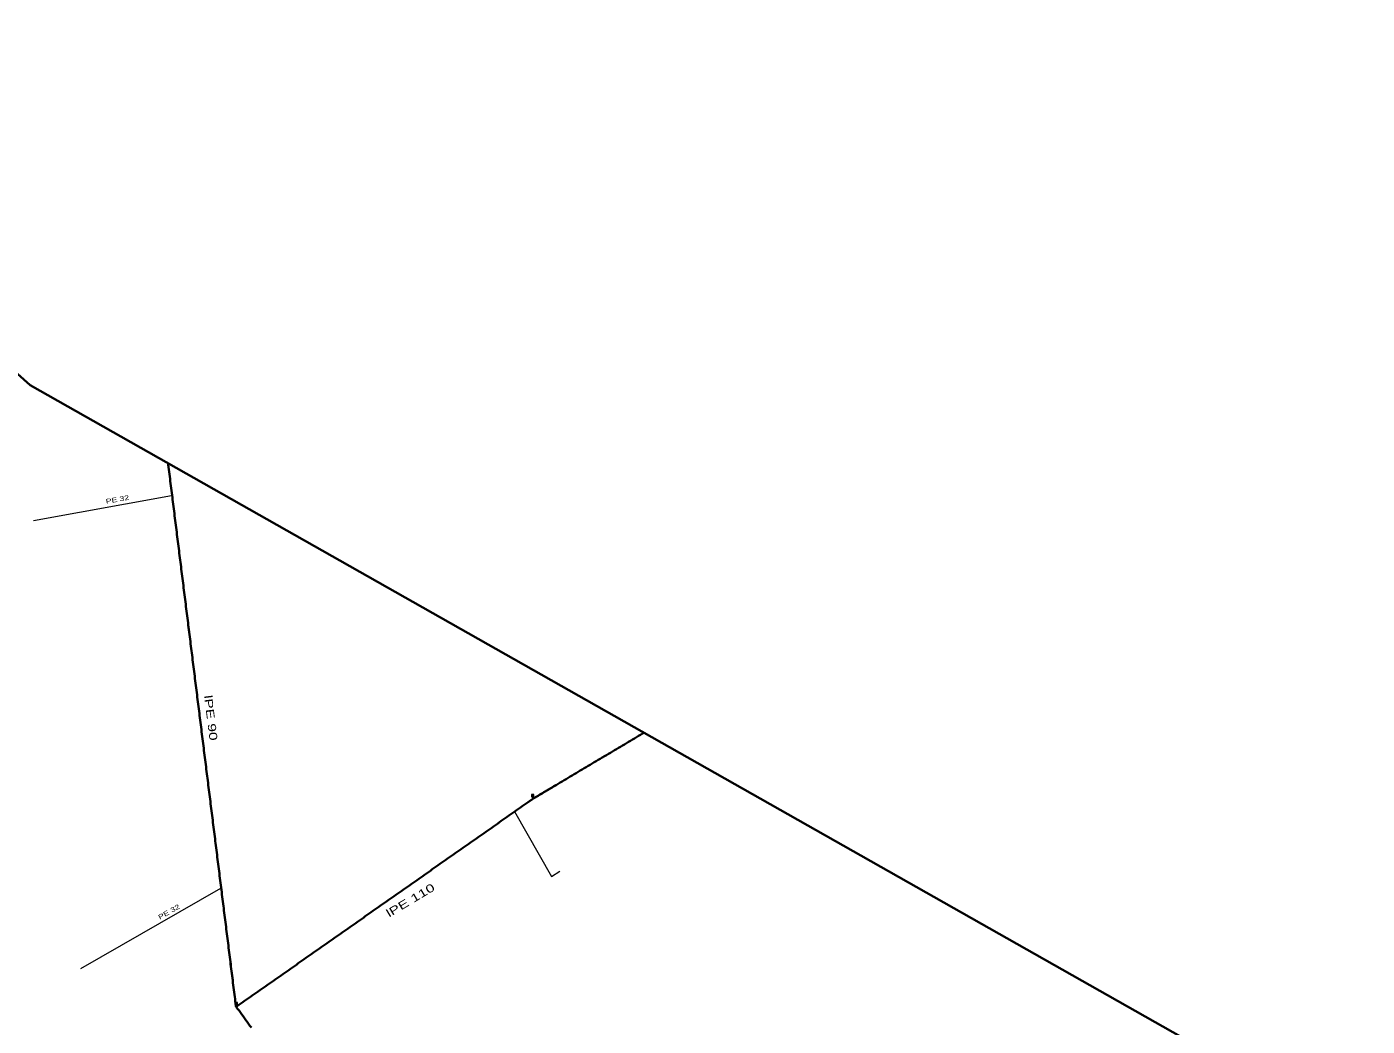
# Model space of a CAD drawing. Extents: x -18.3 to 18.3, y -32.8 to 32.8.
# Drawn here: x 15.245 to 18.281, y 9.754 to 12.016 of the extents above; entities that cross this region are included whole.
import ezdxf

# ---------------------------------------------------------------- set-up
doc = ezdxf.new("R2010")
doc.units = 0
doc.header["$LTSCALE"] = 0.0072
doc.layers.add('16', color=7, linetype='Continuous')
doc.layers.add('18', color=7, linetype='Continuous')
for name, color, linetype, lineweight in [('28', 7, 'Continuous', 13), ('29', 7, 'Continuous', 13), ('5', 7, 'Continuous', 35), ('63', 7, 'Continuous', 35)]:
    doc.layers.add(name, color=color, linetype=linetype, lineweight=lineweight)

msp = doc.modelspace()

# ---------------------------------------------------------------- linework, layer by layer
at = {"layer": '28'}
for points in [[(15.574458, 10.954562), (15.573062, 10.95426), (15.26026, 10.897958)], [(16.349958, 10.23926), (16.433865, 10.092458), (16.452458, 10.104354)], [(15.685656, 10.065156), (15.684156, 10.065062), (15.36726, 9.883656)]]:
    msp.add_lwpolyline(points, dxfattribs=at)
at = {"layer": '29'}
for p, q in [((16.391063, 10.268062), (16.391063, 10.277979)), ((15.71976, 9.797458), (15.71976, 9.807375))]:
    msp.add_line(p, q, dxfattribs=at)
for points in [[(16.388542, 10.277979), (16.388542, 10.273094), (16.393583, 10.273094), (16.393583, 10.277979)], [(16.391531, 10.27751), (16.393115, 10.27751), (16.393115, 10.273573), (16.391531, 10.273573)], [(16.392, 10.277042), (16.392, 10.274042), (16.392635, 10.274042), (16.392635, 10.277042)], [(15.71724, 9.807375), (15.71724, 9.8025), (15.722281, 9.8025), (15.722281, 9.807375)], [(15.720229, 9.806906), (15.721812, 9.806906), (15.721812, 9.802969), (15.720229, 9.802969)], [(15.720698, 9.806437), (15.720698, 9.803437), (15.721333, 9.803437), (15.721333, 9.806437)]]:
    msp.add_lwpolyline(points, close=True, dxfattribs=at)
at = {"layer": '5'}
for q in [(15.718865, 9.799156), (15.721365, 9.798562)]:
    msp.add_line((15.71976, 9.797458), q, dxfattribs=at)
for points in [[(15.565281, 11.027844), (15.565719, 11.024396), (15.566375, 11.019146), (15.567031, 11.013896), (15.567687, 11.008635), (15.568344, 11.003385), (15.569, 10.998125), (15.569667, 10.992875), (15.570323, 10.987615), (15.570979, 10.982365), (15.571635, 10.977104), (15.572292, 10.971854), (15.572948, 10.966594), (15.573615, 10.961344), (15.574271, 10.956083), (15.574927, 10.950833), (15.575583, 10.945573), (15.57624, 10.940323), (15.576896, 10.935062), (15.577552, 10.929812), (15.578208, 10.924563), (15.578865, 10.919302), (15.579521, 10.914052), (15.580187, 10.908792), (15.580844, 10.903542), (15.5815, 10.898281), (15.582156, 10.893031), (15.582812, 10.887771), (15.583469, 10.882521), (15.584125, 10.87726), (15.584781, 10.87201), (15.585437, 10.86675), (15.586094, 10.8615), (15.58675, 10.85624), (15.587406, 10.85099), (15.588062, 10.845729), (15.588719, 10.840479), (15.589385, 10.835219), (15.590042, 10.829969), (15.590698, 10.824708), (15.591354, 10.819458), (15.59201, 10.814198), (15.592667, 10.808948), (15.593323, 10.803687), (15.593979, 10.798438), (15.594635, 10.793188), (15.595292, 10.787927), (15.595948, 10.782677), (15.596604, 10.777417), (15.59726, 10.772167), (15.597927, 10.766906), (15.598583, 10.761656), (15.59924, 10.756396), (15.599896, 10.751146), (15.600552, 10.745885), (15.601208, 10.740635), (15.601865, 10.735375), (15.602521, 10.730125), (15.603177, 10.724865), (15.603833, 10.719615), (15.60449, 10.714354), (15.605146, 10.709104), (15.605802, 10.703844), (15.606458, 10.698594), (15.607125, 10.693333), (15.607781, 10.688083), (15.608437, 10.682823), (15.609094, 10.677573), (15.60975, 10.672313), (15.610406, 10.667063), (15.611062, 10.661812), (15.611719, 10.656552), (15.612375, 10.651302), (15.613031, 10.646042)], [(15.603219, 10.724552), (15.603875, 10.719302), (15.604531, 10.714042), (15.605187, 10.708792), (15.605844, 10.703531), (15.6065, 10.698281), (15.607156, 10.693021), (15.607812, 10.687771), (15.608469, 10.68251), (15.609135, 10.67726), (15.609792, 10.672), (15.610448, 10.66675), (15.611104, 10.66149), (15.61176, 10.65624), (15.612417, 10.650979), (15.613073, 10.645729), (15.613729, 10.640469), (15.614385, 10.635219), (15.615042, 10.629958), (15.615698, 10.624708), (15.616354, 10.619448), (15.61701, 10.614198), (15.617677, 10.608937), (15.618333, 10.603687), (15.61899, 10.598437), (15.619646, 10.593177), (15.620302, 10.587927), (15.620958, 10.582667), (15.621615, 10.577417), (15.622271, 10.572156), (15.622927, 10.566906), (15.623583, 10.561646), (15.62424, 10.556396), (15.624896, 10.551135), (15.625552, 10.545885), (15.626219, 10.540625), (15.626875, 10.535375), (15.627531, 10.530115), (15.628187, 10.524865), (15.628844, 10.519604), (15.6295, 10.514354), (15.630156, 10.509094), (15.630812, 10.503844), (15.631469, 10.498583), (15.632125, 10.493333), (15.632781, 10.488073), (15.633437, 10.482823), (15.634094, 10.477562), (15.63475, 10.472312), (15.635417, 10.467062), (15.636073, 10.461802), (15.636729, 10.456552), (15.637385, 10.451292), (15.638042, 10.446042), (15.638698, 10.440781), (15.639354, 10.435531), (15.64001, 10.430271), (15.640667, 10.425021), (15.641323, 10.41976), (15.641979, 10.41451), (15.642635, 10.40925), (15.643292, 10.404), (15.643958, 10.39874), (15.644615, 10.39349), (15.645271, 10.388229), (15.645927, 10.382979), (15.646583, 10.377719), (15.64724, 10.372469), (15.647896, 10.367208), (15.648552, 10.361958), (15.649208, 10.356698), (15.649865, 10.351448), (15.650521, 10.346187), (15.651177, 10.340937), (15.651833, 10.335687), (15.65249, 10.330427), (15.653156, 10.325177), (15.653812, 10.319917), (15.654469, 10.314667), (15.655125, 10.309406), (15.655781, 10.304156), (15.656437, 10.298896), (15.657094, 10.293646), (15.65775, 10.288385), (15.658406, 10.283135), (15.659062, 10.277875), (15.659719, 10.272625), (15.660375, 10.267365), (15.661031, 10.262115), (15.661698, 10.256854), (15.662354, 10.251604), (15.66301, 10.246344), (15.663667, 10.241094), (15.664323, 10.235833), (15.664979, 10.230583), (15.665635, 10.225323), (15.666292, 10.220073)], [(16.376417, 10.257802), (16.38075, 10.260833), (16.385094, 10.263875), (16.389427, 10.266917), (16.393896, 10.26975), (16.398448, 10.272458), (16.403, 10.275167), (16.407552, 10.277875), (16.412104, 10.280583), (16.416656, 10.283292), (16.421208, 10.286), (16.42576, 10.288708), (16.430302, 10.291417), (16.434854, 10.294125), (16.439406, 10.296833), (16.443958, 10.299542), (16.44851, 10.30225), (16.453062, 10.304958), (16.457615, 10.307667), (16.462167, 10.310375), (16.466719, 10.313083), (16.471271, 10.315792), (16.475812, 10.3185), (16.480365, 10.321208), (16.484917, 10.323917), (16.489469, 10.326625), (16.494021, 10.329333), (16.498573, 10.332042), (16.503125, 10.33475), (16.507677, 10.337458), (16.512229, 10.340167), (16.516781, 10.342875), (16.521323, 10.345583), (16.525875, 10.348292), (16.530427, 10.351), (16.534979, 10.353708), (16.539531, 10.356417), (16.544083, 10.359125), (16.548635, 10.361833), (16.553187, 10.364542), (16.55774, 10.36725), (16.562281, 10.369958), (16.566833, 10.372667), (16.571385, 10.375375), (16.575937, 10.378083), (16.58049, 10.380792), (16.585042, 10.3835), (16.589594, 10.386208), (16.594146, 10.388917), (16.598698, 10.391625), (16.60325, 10.394333), (16.607792, 10.397042), (16.612344, 10.39975), (16.616896, 10.402458), (16.621448, 10.405167), (16.626, 10.407875), (16.630552, 10.410583), (16.635104, 10.413292), (16.639656, 10.416), (16.643052, 10.418021)], [(16.137656, 10.090417), (16.14199, 10.093458), (16.146323, 10.09649), (16.150667, 10.099531), (16.155, 10.102573), (16.159333, 10.105615), (16.163667, 10.108656), (16.16801, 10.111698), (16.172344, 10.11474), (16.176677, 10.117771), (16.181021, 10.120812), (16.185354, 10.123854), (16.189687, 10.126896), (16.194021, 10.129938), (16.198365, 10.132979), (16.202698, 10.13601), (16.207031, 10.139052), (16.211375, 10.142094), (16.215708, 10.145135), (16.220042, 10.148177), (16.224375, 10.151219), (16.228719, 10.15426), (16.233052, 10.157292), (16.237385, 10.160333), (16.241729, 10.163375), (16.246063, 10.166417), (16.250396, 10.169458), (16.25474, 10.1725), (16.259073, 10.175542), (16.263406, 10.178573), (16.26774, 10.181615), (16.272083, 10.184656), (16.276417, 10.187698), (16.28075, 10.19074), (16.285094, 10.193781), (16.289427, 10.196823), (16.29376, 10.199854), (16.298094, 10.202896), (16.302437, 10.205937), (16.306771, 10.208979), (16.311104, 10.212021), (16.315448, 10.215063), (16.319781, 10.218104), (16.324115, 10.221135), (16.328448, 10.224177), (16.332792, 10.227219), (16.337125, 10.23026), (16.341458, 10.233302), (16.345802, 10.236344), (16.350135, 10.239385), (16.354469, 10.242417), (16.358812, 10.245458), (16.363146, 10.2485), (16.367479, 10.251542), (16.371823, 10.254573), (16.376156, 10.257615), (16.38049, 10.260656), (16.384833, 10.263698), (16.389167, 10.266729), (16.393625, 10.269583), (16.398177, 10.272292), (16.402729, 10.275), (16.407281, 10.277708), (16.411833, 10.280417), (16.416385, 10.283125), (16.420927, 10.285833), (16.425479, 10.288542), (16.430031, 10.29125), (16.434583, 10.293958), (16.439135, 10.296667), (16.443687, 10.299375)], [(15.666292, 10.220073), (15.666948, 10.214823), (15.667604, 10.209563), (15.66826, 10.204313), (15.668917, 10.199052), (15.669573, 10.193802), (15.670229, 10.188542), (15.670896, 10.183292), (15.671552, 10.178031), (15.672208, 10.172781), (15.672865, 10.167521), (15.673521, 10.162271), (15.674177, 10.15701), (15.674833, 10.15176), (15.67549, 10.1465), (15.676146, 10.14125), (15.676802, 10.13599), (15.677458, 10.13074), (15.678115, 10.125479), (15.678771, 10.120229), (15.679437, 10.114969), (15.680094, 10.109719), (15.68075, 10.104458), (15.681406, 10.099208), (15.682062, 10.093948), (15.682719, 10.088698), (15.683375, 10.083448), (15.684031, 10.078188), (15.684687, 10.072938), (15.685344, 10.067677), (15.686, 10.062427), (15.686656, 10.057167), (15.687312, 10.051917), (15.687969, 10.046656), (15.688625, 10.041406), (15.689281, 10.036146), (15.689937, 10.030896), (15.690594, 10.025635), (15.69125, 10.020385), (15.691906, 10.015125), (15.692562, 10.009875), (15.693219, 10.004615), (15.693875, 9.999365), (15.694531, 9.994104), (15.695187, 9.988854), (15.695844, 9.983594), (15.6965, 9.978344), (15.697156, 9.973083), (15.697812, 9.967833), (15.698469, 9.962573), (15.699125, 9.957323), (15.699771, 9.952063), (15.700427, 9.946813), (15.701083, 9.941552), (15.70174, 9.936302), (15.702396, 9.931042), (15.703052, 9.925792), (15.703708, 9.920531), (15.704365, 9.915281), (15.705021, 9.910021), (15.705677, 9.904771), (15.706333, 9.89951), (15.70699, 9.89426), (15.707646, 9.889), (15.708302, 9.88375), (15.708958, 9.87849), (15.709615, 9.87324), (15.710271, 9.867979), (15.710927, 9.862729), (15.711583, 9.857469), (15.71224, 9.852219)], [(15.721365, 9.798562), (15.725698, 9.801594), (15.730031, 9.804635), (15.734365, 9.807677), (15.738708, 9.810719), (15.743042, 9.81376), (15.747375, 9.816802), (15.751719, 9.819844), (15.756052, 9.822875), (15.760385, 9.825917), (15.764729, 9.828958), (15.769062, 9.832), (15.773396, 9.835042), (15.777729, 9.838083), (15.782073, 9.841125), (15.786406, 9.844156), (15.79074, 9.847198), (15.795083, 9.85024), (15.799417, 9.853281), (15.80375, 9.856323), (15.808083, 9.859365), (15.812427, 9.862406), (15.81676, 9.865438), (15.821094, 9.868479), (15.825437, 9.871521), (15.829771, 9.874562), (15.834104, 9.877604), (15.838437, 9.880646), (15.842781, 9.883687), (15.847115, 9.886719), (15.851448, 9.88976), (15.855792, 9.892802), (15.860125, 9.895844), (15.864458, 9.898885), (15.868802, 9.901927), (15.873135, 9.904969), (15.877469, 9.908), (15.881802, 9.911042), (15.886146, 9.914083), (15.890479, 9.917125), (15.894812, 9.920167), (15.899156, 9.923208), (15.90349, 9.92625), (15.907823, 9.929281), (15.912156, 9.932323), (15.9165, 9.935365), (15.920833, 9.938406), (15.925167, 9.941448), (15.92951, 9.94449), (15.933844, 9.947521), (15.938177, 9.950563), (15.94251, 9.953604), (15.946854, 9.956646), (15.951187, 9.959687), (15.955521, 9.962729), (15.959865, 9.965771), (15.964198, 9.968802), (15.968531, 9.971844), (15.972875, 9.974885), (15.977208, 9.977927), (15.981542, 9.980969), (15.985875, 9.98401), (15.990219, 9.987052), (15.994552, 9.990083), (15.998885, 9.993125), (16.003229, 9.996167), (16.007562, 9.999208), (16.011896, 10.00225), (16.016229, 10.005292), (16.020573, 10.008333), (16.024906, 10.011365), (16.02924, 10.014406), (16.033583, 10.017448), (16.037917, 10.02049), (16.04225, 10.023531), (16.046583, 10.026573), (16.050927, 10.029615), (16.05526, 10.032646), (16.059594, 10.035687), (16.063937, 10.038729), (16.068271, 10.041771), (16.072604, 10.044812), (16.076948, 10.047854), (16.081281, 10.050896), (16.085615, 10.053927), (16.089948, 10.056969), (16.094292, 10.06001), (16.098625, 10.063052), (16.102958, 10.066094), (16.107302, 10.069135), (16.111635, 10.072177), (16.115969, 10.075208), (16.120302, 10.07825), (16.124646, 10.081292), (16.128979, 10.084333), (16.133312, 10.087375), (16.137656, 10.090417)], [(15.702438, 9.930729), (15.703094, 9.925479), (15.70375, 9.920219), (15.704406, 9.914969), (15.705062, 9.909708), (15.705719, 9.904458), (15.706375, 9.899198), (15.707031, 9.893948), (15.707687, 9.888687), (15.708344, 9.883437), (15.709, 9.878177), (15.709656, 9.872927), (15.710312, 9.867667), (15.710969, 9.862417), (15.711625, 9.857156), (15.712281, 9.851906), (15.712937, 9.846646), (15.713594, 9.841396), (15.71425, 9.836135), (15.714906, 9.830885), (15.715552, 9.825625), (15.716208, 9.820375), (15.716865, 9.815115), (15.717521, 9.809865), (15.718177, 9.804604), (15.718833, 9.799354), (15.718865, 9.799156)], [(15.71976, 9.797458), (15.722865, 9.793167), (15.725958, 9.788875), (15.729062, 9.784583), (15.732167, 9.780292), (15.735271, 9.77599), (15.738365, 9.771698), (15.741469, 9.767406), (15.744573, 9.763115), (15.747667, 9.758823), (15.750771, 9.754531), (15.753875, 9.75024)]]:
    msp.add_lwpolyline(points, dxfattribs=at)
at = {"layer": '63'}
msp.add_lwpolyline([(6.821417, -12.034073), (10.570802, 1.718333), (16.15951, 8.231344), (14.281458, 9.78576), (7.75526, 16.244156), (2.207979, 21.642292), (-4.211323, 25.162208), (-9.541, 28.856333), (-11.476635, 29.828458), (-11.428635, 28.932656), (-12.590438, 28.732062), (-18.280635, 29.748156), (-18.02001, 32.23425), (-12.039885, 32.814354), (-8.624021, 29.362521), (-2.888135, 26.135219), (2.67676, 22.377854), (8.287094, 17.445521), (15.252958, 11.204562), (18.280635, 9.491437), (12.985292, 0.960906), (8.539271, -13.360323)], dxfattribs=at)

# ---------------------------------------------------------------- texts
at = {"layer": '16', "width": 1.45}
for s, rotation, p in [('lPE 90', 277.127, (15.646708, 10.501833)), ('lPE 110', 30.932, (16.065938, 9.999323))]:
    msp.add_text(s, height=0.01812, rotation=rotation, dxfattribs=at).set_placement(p)
at = {"layer": '18', "width": 1.35}
for height, rotation, p in [(0.01087, 10.203, (15.425281, 10.936031)), (0.01088, 29.788, (15.546792, 9.99449))]:
    msp.add_text('PE 32', height=height, rotation=rotation, dxfattribs=at).set_placement(p)

doc.saveas('drawing.dxf')
